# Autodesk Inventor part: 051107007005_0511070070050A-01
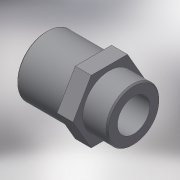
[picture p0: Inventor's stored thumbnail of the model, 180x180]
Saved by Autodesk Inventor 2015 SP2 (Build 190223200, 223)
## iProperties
Created: 2017-05
Part Number: 051107007005_0511070070050A-01
Material: Generic
Description: PLASSON THREADED REDUCING SOCKET 3/4"-1/2"
Document SubType Name: Modeling
Designer: KIM
Mass: 27.8893 g
Surface Area: 103.254 cm^2
Volume: 27.8893 cm^3
Density: 1 g/cm^3
Appearance: Default
Author: KIM
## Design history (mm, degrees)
derived "051107.ipt"
feature "Solid1::051107.ipt"
tag "TaggingFeature1"
body "Solid1"
other parameters: "d1" = 18.631, "d2" = 24.117, "d4" = 19, "d5" = 36, "d6" = 34.2, "d7" = 19.2936, "d8" = 14.9048, "d10" = 1.83333, "d11" = 5.5, "d14" = 0, "d15" = 0.72351, "G_" = 24.117, "G_1" = 18.631, "l_1" = 19, "E_" = 36, "d9" = 11
